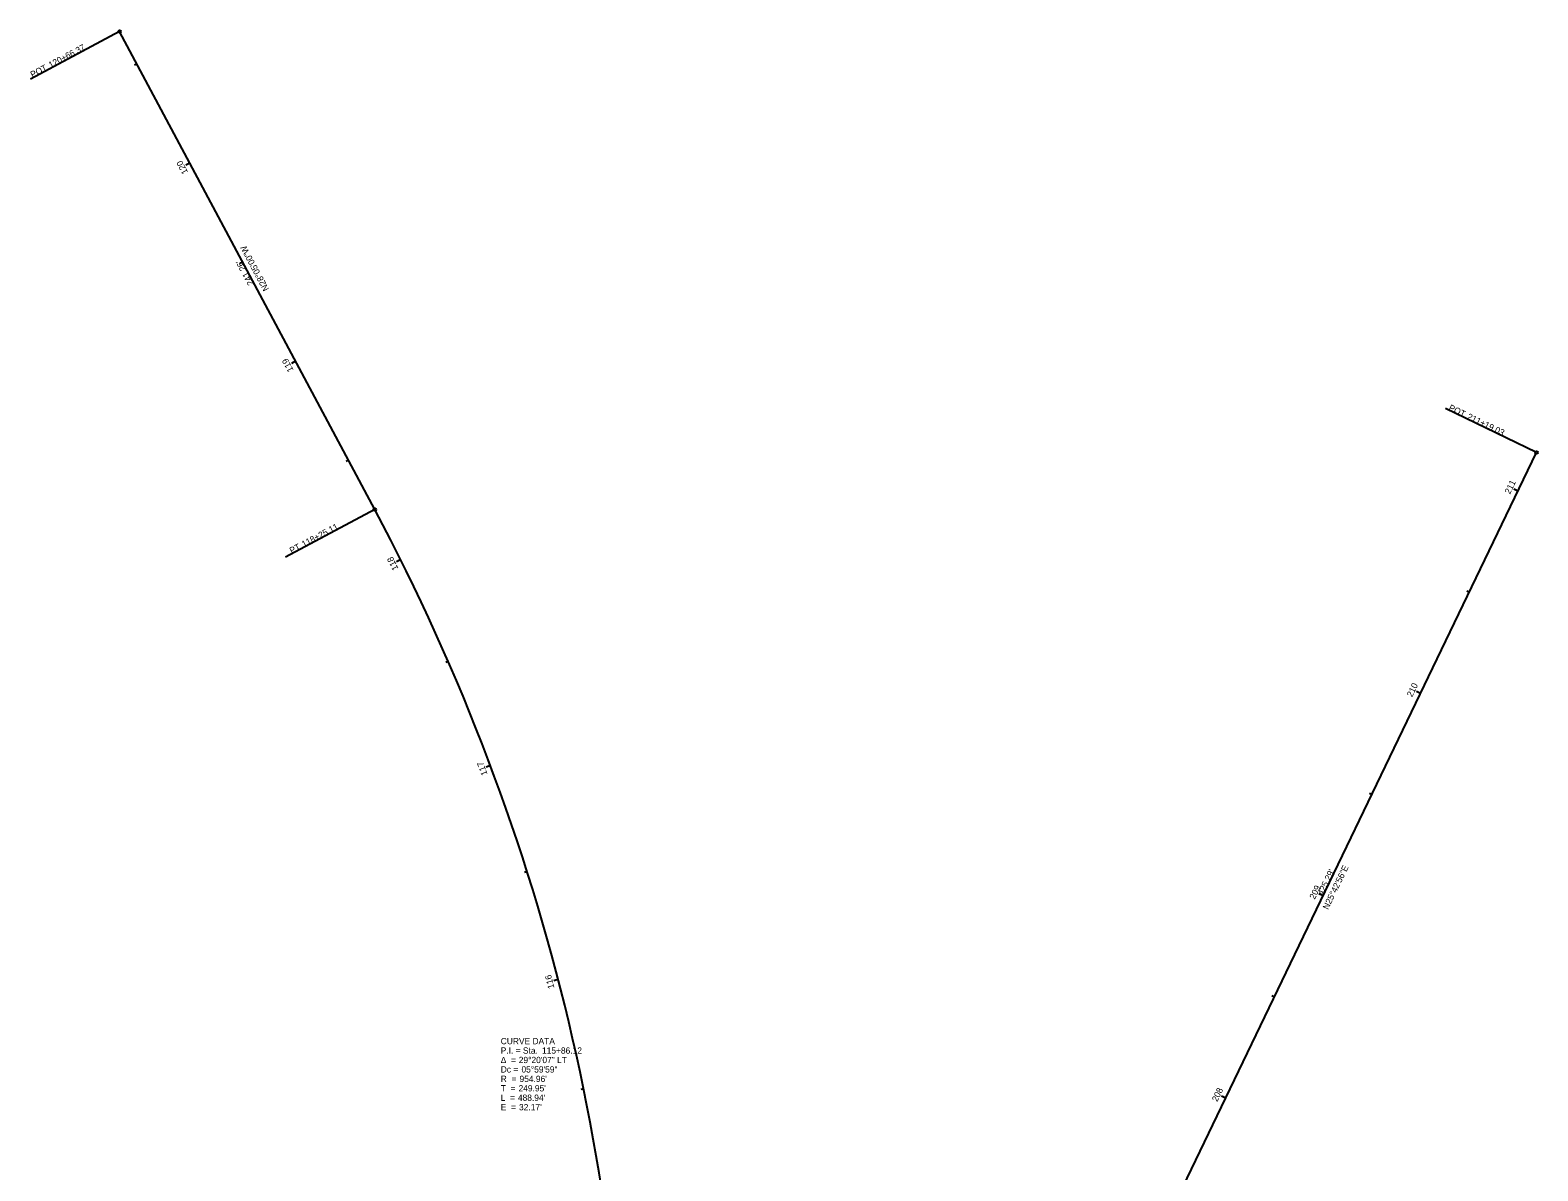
# Model space of a CAD drawing. Extents: x 1564507 to 1565178, y 635740 to 637470.
# Drawn here: x 1564507 to 1565178, y 636962 to 637470 of the extents above; entities that cross this region are included whole.
import ezdxf

# ---------------------------------------------------------------- set-up
doc = ezdxf.new("R2010")
doc.units = 0
for name, color, linetype in [('_CIVIL_CONSTRUCTION', 7, 'Continuous'), ('PM_P_CL_Double_Solid', 7, 'Continuous'), ('PM_P_Edge_Line', 7, 'Continuous'), ('PV_P_Drive', 7, 'Continuous'), ('PV_P_EOP', 7, 'Continuous'), ('PV_P_Shoulder', 7, 'Continuous'), ('RD_P_Wall', 7, 'Continuous'), ('RW_P_Const_Limits', 7, 'Continuous'), ('SC_Scratch1', 7, 'Continuous'), ('SC_Scratch2', 7, 'Continuous'), ('SC_Shading1', 7, 'Continuous'), ('SC_Shading3', 7, 'Continuous'), ('TR_Turning_Path2', 7, 'Continuous'), ('TR_Turning_Path5', 7, 'Continuous'), ('TR_Turning_Path6', 7, 'Continuous'), ('VG_P_Landscape_Limits', 7, 'Continuous')]:
    doc.layers.add(name, color=color, linetype=linetype)

msp = doc.modelspace()

# ---------------------------------------------------------------- linework, layer by layer
at = {"layer": '_CIVIL_CONSTRUCTION'}
for p, q in [((1564577.72, 637410.98), (1564575.96, 637410.04)), ((1565125.67, 637174.87), (1565123.87, 637175.74))]:
    msp.add_line(p, q, dxfattribs=at)
at = {"layer": 'PM_P_CL_Double_Solid'}
for p, q in [((1564554.19, 637455.09), (1564553.13, 637454.53)), ((1564577.72, 637410.98), (1564575.96, 637410.04)), ((1564601.26, 637366.87), (1564600.2, 637366.3)), ((1564624.8, 637322.75), (1564623.04, 637321.81)), ((1564648.34, 637278.64), (1564647.28, 637278.08)), ((1565169.06, 637264.97), (1565167.26, 637265.83)), ((1564671.58, 637234.37), (1564669.79, 637233.48)), ((1565147.37, 637219.92), (1565146.29, 637220.44)), ((1564692.77, 637189.09), (1564691.67, 637188.61)), ((1565125.67, 637174.87), (1565123.87, 637175.74)), ((1564711.56, 637142.76), (1564709.69, 637142.06)), ((1565103.98, 637129.82), (1565102.9, 637130.34)), ((1564727.9, 637095.52), (1564726.76, 637095.15)), ((1565082.28, 637084.78), (1565080.48, 637085.64)), ((1564741.75, 637047.48), (1564739.81, 637046.97)), ((1565060.59, 637039.73), (1565059.51, 637040.25)), ((1564753.06, 636998.78), (1564751.88, 636998.54)), ((1565038.89, 636994.68), (1565037.09, 636995.55))]:
    msp.add_line(p, q, dxfattribs=at)
at = {"layer": 'PV_P_EOP'}
for p, q in [((1564546.48, 637469.54), (1564506.78, 637448.35)), ((1565177.32, 637282.11), (1565136.78, 637301.64)), ((1564660.06, 637256.68), (1564620.35, 637235.5))]:
    msp.add_line(p, q, dxfattribs=at)
for centre in [(1564546.48, 637469.54), (1565177.32, 637282.11), (1564660.06, 637256.68)]:
    msp.add_circle(centre, 0.6, dxfattribs=at)
at = {"layer": 'PV_P_Shoulder'}
for p, q in [((1564546.48, 637469.54), (1564506.78, 637448.35)), ((1565177.32, 637282.11), (1565136.78, 637301.64)), ((1564660.06, 637256.68), (1564620.35, 637235.5))]:
    msp.add_line(p, q, dxfattribs=at)
for centre in [(1564546.48, 637469.54), (1565177.32, 637282.11), (1564660.06, 637256.68)]:
    msp.add_circle(centre, 0.6, dxfattribs=at)
at = {"layer": 'SC_Scratch2'}
for p, q in [((1564577.72, 637410.98), (1564575.96, 637410.04)), ((1564624.8, 637322.75), (1564623.74, 637322.19)), ((1565169.06, 637264.97), (1565167.98, 637265.49)), ((1564671.58, 637234.37), (1564670.51, 637233.84)), ((1565125.67, 637174.87), (1565123.87, 637175.74)), ((1564711.56, 637142.76), (1564710.44, 637142.34)), ((1565082.28, 637084.78), (1565081.2, 637085.3)), ((1564741.75, 637047.48), (1564740.59, 637047.17)), ((1565038.89, 636994.68), (1565037.81, 636995.2))]:
    msp.add_line(p, q, dxfattribs=at)
at = {"layer": 'SC_Shading3'}
for p, q in [((1564546.48, 637469.54), (1564506.78, 637448.35)), ((1565177.32, 637282.11), (1565136.78, 637301.64)), ((1564660.06, 637256.68), (1564620.35, 637235.5))]:
    msp.add_line(p, q, dxfattribs=at)
for centre in [(1564546.48, 637469.54), (1565177.32, 637282.11), (1564660.06, 637256.68)]:
    msp.add_circle(centre, 0.6, dxfattribs=at)
at = {"layer": 'TR_Turning_Path2'}
for p, q in [((1564660.06, 637256.68), (1564546.48, 637469.54)), ((1564660.06, 637256.68), (1564546.48, 637469.54)), ((1564992.79, 636898.95), (1565177.32, 637282.11)), ((1564992.79, 636898.95), (1565177.32, 637282.11))]:
    msp.add_line(p, q, dxfattribs=at)
msp.add_arc((1563817.53, 636807.13), 954.96, 358.74802, 28.08321, dxfattribs=at)
msp.add_arc((1563817.53, 636807.13), 954.96, 358.74802, 28.08321, dxfattribs=at)

# ---------------------------------------------------------------- texts
at = {"layer": '_CIVIL_CONSTRUCTION'}
for s, rotation, p in [('120', 118.08321, (1564577.02, 637406.89)), ('210', 64.28444, (1565121.95, 637173.02))]:
    msp.add_text(s, height=2.8, rotation=rotation, dxfattribs=at).set_placement(p)
at = {"layer": 'PM_P_CL_Double_Solid'}
for s, rotation, p in [('120', 118.08321, (1564577.02, 637406.89)), ('119', 118.08321, (1564624.02, 637318.81)), ('211', 64.28444, (1565165.52, 637263.38)), ('118', 116.57679, (1564670.71, 637230.43)), ('210', 64.28444, (1565121.95, 637173.02)), ('117', 110.57698, (1564710.35, 637138.9)), ('209', 64.28444, (1565078.58, 637082.95)), ('116', 104.57717, (1564740.07, 637043.8)), ('208', 64.28444, (1565035.17, 636992.83))]:
    msp.add_text(s, height=2.8, rotation=rotation, dxfattribs=at).set_placement(p)
at = {"layer": 'PM_P_Edge_Line'}
for s, rotation, p in [('N28°05\'00"W', 118.08321, (1564613.09, 637354.9)), ('N25°42\'56"E', 64.28444, (1565084.53, 637078.37))]:
    msp.add_text(s, height=2.8, rotation=rotation, dxfattribs=at).set_placement(p)
at = {"layer": 'PV_P_Drive'}
for s, p in [('CURVE DATA', (1564716.16, 637018.67)), ('Δ  = ', (1564716.16, 637010.27)), ('P.I. = Sta. ', (1564716.16, 637014.47)), ('29°20\'07" LT', (1564724.18, 637010.27)), ('115+86.12', (1564734.53, 637014.47)), ('Dc = ', (1564716.16, 637006.07)), ('R  = ', (1564716.16, 637001.87)), ("954.96'", (1564724.53, 637001.87)), ('05°59\'59"', (1564725.4, 637006.07)), ('T  = ', (1564716.16, 636997.67)), ("249.95'", (1564724.09, 636997.67)), ('L  = ', (1564716.16, 636993.47)), ('E  = ', (1564716.16, 636989.27)), ("488.94'", (1564723.81, 636993.47)), ("32.17'", (1564724.31, 636989.27))]:
    msp.add_text(s, height=2.8, dxfattribs=at).set_placement(p)
at = {"layer": 'PV_P_EOP'}
for s, rotation, p in [('120+66.37', 28.08321, (1564515.75, 637453.19)), ('POT', 28.08321, (1564507.69, 637448.89)), ('POT', 334.28444, (1565137.95, 637301.12)), ('211+19.03', 334.28444, (1565146.18, 637297.16)), ('118+25.11', 28.08321, (1564628.44, 637239.86)), ('PT', 28.08321, (1564623.07, 637237))]:
    msp.add_text(s, height=2.8, rotation=rotation, dxfattribs=at).set_placement(p)
at = {"layer": 'PV_P_Shoulder'}
for s, rotation, p in [('120+66.37', 28.08321, (1564515.75, 637453.19)), ('POT', 28.08321, (1564507.69, 637448.89)), ('POT', 334.28444, (1565137.95, 637301.12)), ('211+19.03', 334.28444, (1565146.18, 637297.16)), ('118+25.11', 28.08321, (1564628.44, 637239.86)), ('PT', 28.08321, (1564623.07, 637237))]:
    msp.add_text(s, height=2.8, rotation=rotation, dxfattribs=at).set_placement(p)
at = {"layer": 'RD_P_Wall'}
for s, rotation, p in [("241.26'", 118.08321, (1564606.28, 637357.36)), ("425.29'", 64.28444, (1565082.2, 637084.71))]:
    msp.add_text(s, height=2.8, rotation=rotation, dxfattribs=at).set_placement(p)
at = {"layer": 'RW_P_Const_Limits'}
for s, rotation, p in [("241.26'", 118.08321, (1564606.28, 637357.36)), ("425.29'", 64.28444, (1565082.2, 637084.71))]:
    msp.add_text(s, height=2.8, rotation=rotation, dxfattribs=at).set_placement(p)
at = {"layer": 'SC_Scratch1'}
for s, rotation, p in [("241.26'", 118.08321, (1564606.28, 637357.36)), ("425.29'", 64.28444, (1565082.2, 637084.71))]:
    msp.add_text(s, height=2.8, rotation=rotation, dxfattribs=at).set_placement(p)
at = {"layer": 'SC_Scratch2'}
for s, rotation, p in [('120', 118.08321, (1564577.02, 637406.89)), ('210', 64.28444, (1565121.95, 637173.02))]:
    msp.add_text(s, height=2.8, rotation=rotation, dxfattribs=at).set_placement(p)
at = {"layer": 'SC_Shading1'}
for s, rotation, p in [('N28°05\'00"W', 118.08321, (1564613.09, 637354.9)), ('N25°42\'56"E', 64.28444, (1565084.53, 637078.37))]:
    msp.add_text(s, height=2.8, rotation=rotation, dxfattribs=at).set_placement(p)
at = {"layer": 'SC_Shading3'}
for s, rotation, p in [('120+66.37', 28.08321, (1564515.75, 637453.19)), ('POT', 28.08321, (1564507.69, 637448.89)), ('POT', 334.28444, (1565137.95, 637301.12)), ('211+19.03', 334.28444, (1565146.18, 637297.16)), ('118+25.11', 28.08321, (1564628.44, 637239.86)), ('PT', 28.08321, (1564623.07, 637237))]:
    msp.add_text(s, height=2.8, rotation=rotation, dxfattribs=at).set_placement(p)
at = {"layer": 'TR_Turning_Path5'}
for s, rotation, p in [('N28°05\'00"W', 118.08321, (1564613.09, 637354.9)), ('N25°42\'56"E', 64.28444, (1565084.53, 637078.37))]:
    msp.add_text(s, height=2.8, rotation=rotation, dxfattribs=at).set_placement(p)
at = {"layer": 'TR_Turning_Path6'}
for s, p in [('CURVE DATA', (1564716.16, 637018.67)), ('Δ  = ', (1564716.16, 637010.27)), ('P.I. = Sta. ', (1564716.16, 637014.47)), ('29°20\'07" LT', (1564724.18, 637010.27)), ('115+86.12', (1564734.53, 637014.47)), ('Dc = ', (1564716.16, 637006.07)), ('R  = ', (1564716.16, 637001.87)), ("954.96'", (1564724.53, 637001.87)), ('05°59\'59"', (1564725.4, 637006.07)), ('T  = ', (1564716.16, 636997.67)), ("249.95'", (1564724.09, 636997.67)), ('L  = ', (1564716.16, 636993.47)), ('E  = ', (1564716.16, 636989.27)), ("488.94'", (1564723.81, 636993.47)), ("32.17'", (1564724.31, 636989.27))]:
    msp.add_text(s, height=2.8, dxfattribs=at).set_placement(p)
at = {"layer": 'VG_P_Landscape_Limits'}
for s, p in [('CURVE DATA', (1564716.16, 637018.67)), ('Δ  = ', (1564716.16, 637010.27)), ('P.I. = Sta. ', (1564716.16, 637014.47)), ('29°20\'07" LT', (1564724.18, 637010.27)), ('115+86.12', (1564734.53, 637014.47)), ('Dc = ', (1564716.16, 637006.07)), ('R  = ', (1564716.16, 637001.87)), ("954.96'", (1564724.53, 637001.87)), ('05°59\'59"', (1564725.4, 637006.07)), ('T  = ', (1564716.16, 636997.67)), ("249.95'", (1564724.09, 636997.67)), ('L  = ', (1564716.16, 636993.47)), ('E  = ', (1564716.16, 636989.27)), ("488.94'", (1564723.81, 636993.47)), ("32.17'", (1564724.31, 636989.27))]:
    msp.add_text(s, height=2.8, dxfattribs=at).set_placement(p)

doc.saveas('drawing.dxf')
